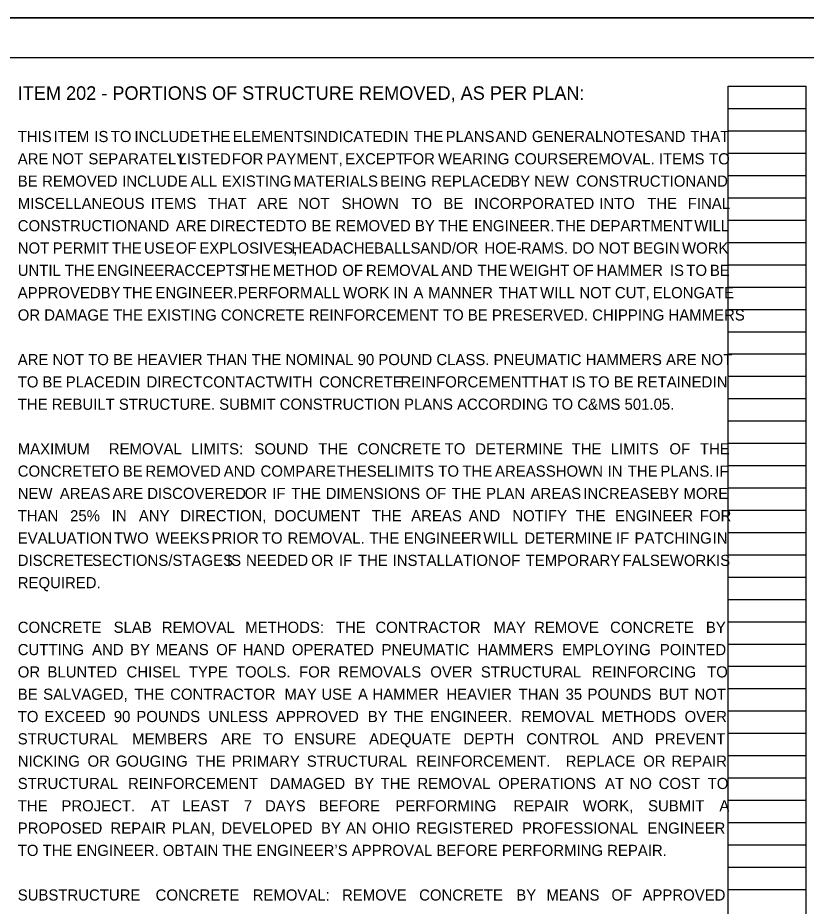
# Model space of a CAD drawing. Extents: x 0 to 64.5, y 0 to 22.
# Drawn here: x 12.29 to 22.19, y 10.85 to 22 of the extents above; entities that cross this region are included whole.
import ezdxf

# ---------------------------------------------------------------- set-up
doc = ezdxf.new("R2010")
doc.units = 0
for name, color, linetype in [('SC_Scratch1', 7, 'Continuous'), ('SH_Border', 7, 'Continuous'), ('SH_Cut_Line', 7, 'Continuous'), ('SH_Text', 7, 'Continuous')]:
    doc.layers.add(name, color=color, linetype=linetype)

msp = doc.modelspace()

# ---------------------------------------------------------------- linework, layer by layer
at = {"layer": 'SC_Scratch1'}
for p, q in [((21.207, 0.98), (21.207, 21.14)), ((21.207, 21.14), (22.187, 21.14)), ((22.187, 0.98), (22.187, 21.14)), ((21.207, 20.86), (22.187, 20.86)), ((21.207, 20.58), (22.187, 20.58)), ((21.207, 20.3), (22.187, 20.3)), ((21.207, 20.02), (22.187, 20.02)), ((21.207, 19.74), (22.187, 19.74)), ((21.207, 19.46), (22.187, 19.46)), ((21.207, 19.18), (22.187, 19.18)), ((21.207, 18.9), (22.187, 18.9)), ((21.207, 18.62), (22.187, 18.62)), ((21.207, 18.34), (22.187, 18.34)), ((21.207, 18.06), (22.187, 18.06)), ((21.207, 17.78), (22.187, 17.78)), ((21.207, 17.5), (22.187, 17.5)), ((21.207, 17.22), (22.187, 17.22)), ((21.207, 16.94), (22.187, 16.94)), ((21.207, 16.66), (22.187, 16.66)), ((21.207, 16.38), (22.187, 16.38)), ((21.207, 16.1), (22.187, 16.1)), ((21.207, 15.82), (22.187, 15.82)), ((21.207, 15.54), (22.187, 15.54)), ((21.207, 15.26), (22.187, 15.26)), ((21.207, 14.98), (22.187, 14.98)), ((21.207, 14.7), (22.187, 14.7)), ((21.207, 14.42), (22.187, 14.42)), ((21.207, 14.14), (22.187, 14.14)), ((21.207, 13.86), (22.187, 13.86)), ((21.207, 13.58), (22.187, 13.58)), ((21.207, 13.3), (22.187, 13.3)), ((21.207, 13.02), (22.187, 13.02)), ((21.207, 12.74), (22.187, 12.74)), ((21.207, 12.46), (22.187, 12.46)), ((21.207, 12.18), (22.187, 12.18)), ((21.207, 11.9), (22.187, 11.9)), ((21.207, 11.62), (22.187, 11.62)), ((21.207, 11.34), (22.187, 11.34)), ((21.207, 11.06), (22.187, 11.06))]:
    msp.add_line(p, q, dxfattribs=at)
msp.add_lwpolyline([(0, 22), (34, 22), (34, 0), (0, 0)], close=True, dxfattribs=at)
at = {"layer": 'SH_Border'}
msp.add_lwpolyline([(1.5, 21.5), (33.5, 21.5), (33.5, 0.5), (1.5, 0.5)], close=True, dxfattribs=at)
at = {"layer": 'SH_Cut_Line'}
msp.add_lwpolyline([(0, 0), (34, 0), (34, 22), (0, 22)], close=True, dxfattribs=at)

# ---------------------------------------------------------------- texts
at = {"layer": 'SH_Text'}
for s, height, p in [('ITEM 202 - PORTIONS OF STRUCTURE REMOVED, AS PER PLAN:', 0.17, (12.293, 20.97)), ('THIS ', 0.14, (12.293, 20.44)), ('ITEM ', 0.14, (12.744, 20.44)), ('IS ', 0.14, (13.254, 20.44)), ('TO ', 0.14, (13.46, 20.44)), ('INCLUDE ', 0.14, (13.757, 20.44)), ('THE ', 0.14, (14.588, 20.44)), ('ELEMENTS ', 0.14, (14.991, 20.44)), ('INDICATED ', 0.14, (15.996, 20.44)), ('IN ', 0.14, (17.011, 20.44)), ('THE ', 0.14, (17.259, 20.44)), ('PLANS ', 0.14, (17.662, 20.44)), ('AND ', 0.14, (18.289, 20.44)), ('GENERAL ', 0.14, (18.745, 20.44)), ('NOTES ', 0.14, (19.633, 20.44)), ('AND ', 0.14, (20.277, 20.44)), ('THAT ', 0.14, (20.733, 20.44)), ('ARE ', 0.14, (12.293, 20.16)), ('NOT ', 0.14, (12.719, 20.16)), ('SEPARATELY ', 0.14, (13.179, 20.16)), ('LISTED ', 0.14, (14.311, 20.16)), ('FOR ', 0.14, (14.98, 20.16)), ('PAYMENT, ', 0.14, (15.414, 20.16)), ('EXCEPT ', 0.14, (16.402, 20.16)), ('FOR ', 0.14, (17.132, 20.16)), ('WEARING ', 0.14, (17.567, 20.16)), ('COURSE ', 0.14, (18.524, 20.16)), ('REMOVAL. ', 0.14, (19.318, 20.16)), ('ITEMS ', 0.14, (20.338, 20.16)), ('TO ', 0.14, (20.968, 20.16)), ('BE ', 0.14, (12.293, 19.88)), ('REMOVED ', 0.14, (12.599, 19.88)), ('INCLUDE ', 0.14, (13.603, 19.88)), ('ALL ', 0.14, (14.462, 19.88)), ('EXISTING ', 0.14, (14.853, 19.88)), ('MATERIALS ', 0.14, (15.752, 19.88)), ('BEING ', 0.14, (16.839, 19.88)), ('REPLACED ', 0.14, (17.481, 19.88)), ('BY ', 0.14, (18.474, 19.88)), ('NEW ', 0.14, (18.774, 19.88)), ('CONSTRUCTION ', 0.14, (19.298, 19.88)), ('AND ', 0.14, (20.809, 19.88)), ('MISCELLANEOUS ', 0.14, (12.293, 19.6)), ('ITEMS ', 0.14, (13.962, 19.6)), ('THAT ', 0.14, (14.679, 19.6)), ('ARE ', 0.14, (15.298, 19.6)), ('NOT ', 0.14, (15.81, 19.6)), ('SHOWN ', 0.14, (16.356, 19.6)), ('TO ', 0.14, (17.231, 19.6)), ('BE ', 0.14, (17.634, 19.6)), ('INCORPORATED ', 0.14, (18.019, 19.6)), ('INTO ', 0.14, (19.589, 19.6)), ('THE ', 0.14, (20.191, 19.6)), ('FINAL ', 0.14, (20.7, 19.6)), ('CONSTRUCTION ', 0.14, (12.293, 19.32)), ('AND ', 0.14, (13.799, 19.32)), ('ARE ', 0.14, (14.277, 19.32)), ('DIRECTED ', 0.14, (14.704, 19.32)), ('TO ', 0.14, (15.659, 19.32)), ('BE ', 0.14, (15.978, 19.32)), ('REMOVED ', 0.14, (16.278, 19.32)), ('BY ', 0.14, (17.277, 19.32)), ('THE ', 0.14, (17.571, 19.32)), ('ENGINEER. ', 0.14, (17.996, 19.32)), ('THE ', 0.14, (19.046, 19.32)), ('DEPARTMENT ', 0.14, (19.471, 19.32)), ('WILL ', 0.14, (20.783, 19.32)), ('NOT ', 0.14, (12.293, 19.04)), ('PERMIT ', 0.14, (12.732, 19.04)), ('THE ', 0.14, (13.475, 19.04)), ('USE ', 0.14, (13.877, 19.04)), ('OF ', 0.14, (14.276, 19.04)), ('EXPLOSIVES, ', 0.14, (14.572, 19.04)), ('HEADACHE ', 0.14, (15.728, 19.04)), ('BALLS ', 0.14, (16.764, 19.04)), ('AND/OR ', 0.14, (17.344, 19.04)), ('HOE-', 0.14, (18.149, 19.04)), ('RAMS. ', 0.14, (18.606, 19.04)), ('DO ', 0.14, (19.248, 19.04)), ('NOT ', 0.14, (19.578, 19.04)), ('BEGIN ', 0.14, (20.016, 19.04)), ('WORK ', 0.14, (20.628, 19.04)), ('UNTIL ', 0.14, (12.293, 18.76)), ('THE ', 0.14, (12.883, 18.76)), ('ENGINEER ', 0.14, (13.287, 18.76)), ('ACCEPTS ', 0.14, (14.259, 18.76)), ('THE ', 0.14, (15.091, 18.76)), ('METHOD ', 0.14, (15.494, 18.76)), ('OF ', 0.14, (16.366, 18.76)), ('REMOVAL ', 0.14, (16.662, 18.76)), ('AND ', 0.14, (17.606, 18.76)), ('THE ', 0.14, (18.062, 18.76)), ('WEIGHT ', 0.14, (18.465, 18.76)), ('OF ', 0.14, (19.259, 18.76)), ('HAMMER ', 0.14, (19.556, 18.76)), ('IS ', 0.14, (20.476, 18.76)), ('TO ', 0.14, (20.682, 18.76)), ('BE ', 0.14, (20.978, 18.76)), ('APPROVED ', 0.14, (12.293, 18.48)), ('BY ', 0.14, (13.333, 18.48)), ('THE ', 0.14, (13.611, 18.48)), ('ENGINEER. ', 0.14, (14.021, 18.48)), ('PERFORM ', 0.14, (15.055, 18.48)), ('ALL ', 0.14, (16.005, 18.48)), ('WORK ', 0.14, (16.375, 18.48)), ('IN ', 0.14, (17.005, 18.48)), ('A ', 0.14, (17.259, 18.48)), ('MANNER ', 0.14, (17.444, 18.48)), ('THAT ', 0.14, (18.328, 18.48)), ('WILL ', 0.14, (18.847, 18.48)), ('NOT ', 0.14, (19.341, 18.48)), ('CUT, ', 0.14, (19.786, 18.48)), ('ELONGATE ', 0.14, (20.262, 18.48)), ('OR DAMAGE THE EXISTING CONCRETE REINFORCEMENT TO BE PRESERVED. CHIPPING HAMMERS ', 0.14, (12.293, 18.2)), ('ARE NOT TO BE HEAVIER THAN THE NOMINAL 90 POUND CLASS. PNEUMATIC HAMMERS ARE NOT ', 0.14, (12.293, 17.64)), ('TO ', 0.14, (12.293, 17.36)), ('BE ', 0.14, (12.603, 17.36)), ('PLACED ', 0.14, (12.895, 17.36)), ('IN ', 0.14, (13.647, 17.36)), ('DIRECT ', 0.14, (13.909, 17.36)), ('CONTACT ', 0.14, (14.612, 17.36)), ('WITH ', 0.14, (15.513, 17.36)), ('CONCRETE ', 0.14, (16.074, 17.36)), ('REINFORCEMENT ', 0.14, (17.095, 17.36)), ('THAT ', 0.14, (18.715, 17.36)), ('IS ', 0.14, (19.241, 17.36)), ('TO ', 0.14, (19.46, 17.36)), ('BE ', 0.14, (19.77, 17.36)), ('RETAINED ', 0.14, (20.062, 17.36)), ('IN ', 0.14, (21.013, 17.36)), ('THE REBUILT STRUCTURE. SUBMIT CONSTRUCTION PLANS ACCORDING TO C&MS 501.05. ', 0.14, (12.293, 17.08)), ('MAXIMUM ', 0.14, (12.293, 16.52)), ('REMOVAL ', 0.14, (13.436, 16.52)), ('LIMITS: ', 0.14, (14.467, 16.52)), ('SOUND ', 0.14, (15.263, 16.52)), ('THE ', 0.14, (16.064, 16.52)), ('CONCRETE ', 0.14, (16.554, 16.52)), ('TO ', 0.14, (17.65, 16.52)), ('DETERMINE ', 0.14, (18.033, 16.52)), ('THE ', 0.14, (19.243, 16.52)), ('LIMITS ', 0.14, (19.733, 16.52)), ('OF ', 0.14, (20.47, 16.52)), ('THE ', 0.14, (20.853, 16.52)), ('CONCRETE ', 0.14, (12.293, 16.24)), ('TO ', 0.14, (13.308, 16.24)), ('BE ', 0.14, (13.611, 16.24)), ('REMOVED ', 0.14, (13.895, 16.24)), ('AND ', 0.14, (14.878, 16.24)), ('COMPARE ', 0.14, (15.34, 16.24)), ('THESE ', 0.14, (16.298, 16.24)), ('LIMITS ', 0.14, (16.913, 16.24)), ('TO ', 0.14, (17.57, 16.24)), ('THE ', 0.14, (17.873, 16.24)), ('AREAS ', 0.14, (18.282, 16.24)), ('SHOWN ', 0.14, (18.919, 16.24)), ('IN ', 0.14, (19.693, 16.24)), ('THE ', 0.14, (19.948, 16.24)), ('PLANS. ', 0.14, (20.357, 16.24)), ('IF ', 0.14, (21.046, 16.24)), ('NEW ', 0.14, (12.293, 15.96)), ('AREAS ', 0.14, (12.821, 15.96)), ('ARE ', 0.14, (13.482, 15.96)), ('DISCOVERED ', 0.14, (13.918, 15.96)), ('OR ', 0.14, (15.141, 15.96)), ('IF ', 0.14, (15.486, 15.96)), ('THE ', 0.14, (15.724, 15.96)), ('DIMENSIONS ', 0.14, (16.157, 15.96)), ('OF ', 0.14, (17.41, 15.96)), ('THE ', 0.14, (17.737, 15.96)), ('PLAN ', 0.14, (18.17, 15.96)), ('AREAS ', 0.14, (18.728, 15.96)), ('INCREASE ', 0.14, (19.389, 15.96)), ('BY ', 0.14, (20.343, 15.96)), ('MORE ', 0.14, (20.646, 15.96)), ('THAN ', 0.14, (12.293, 15.68)), ('25% ', 0.14, (12.95, 15.68)), ('IN ', 0.14, (13.473, 15.68)), ('ANY ', 0.14, (13.813, 15.68)), ('DIRECTION, ', 0.14, (14.332, 15.68)), ('DOCUMENT ', 0.14, (15.51, 15.68)), ('THE ', 0.14, (16.735, 15.68)), ('AREAS ', 0.14, (17.23, 15.68)), ('AND ', 0.14, (17.952, 15.68)), ('NOTIFY ', 0.14, (18.499, 15.68)), ('THE ', 0.14, (19.294, 15.68)), ('ENGINEER ', 0.14, (19.788, 15.68)), ('FOR ', 0.14, (20.852, 15.68)), ('EVALUATION ', 0.14, (12.293, 15.4)), ('TWO ', 0.14, (13.5, 15.4)), ('WEEKS ', 0.14, (14.024, 15.4)), ('PRIOR ', 0.14, (14.725, 15.4)), ('TO ', 0.14, (15.356, 15.4)), ('REMOVAL. ', 0.14, (15.679, 15.4)), ('THE ', 0.14, (16.706, 15.4)), ('ENGINEER ', 0.14, (17.136, 15.4)), ('WILL ', 0.14, (18.135, 15.4)), ('DETERMINE ', 0.14, (18.65, 15.4)), ('IF ', 0.14, (19.799, 15.4)), ('PATCHING ', 0.14, (20.033, 15.4)), ('IN ', 0.14, (21.013, 15.4)), ('DISCRETE ', 0.14, (12.293, 15.12)), ('SECTIONS/STAGES ', 0.14, (13.225, 15.12)), ('IS ', 0.14, (14.919, 15.12)), ('NEEDED ', 0.14, (15.157, 15.12)), ('OR ', 0.14, (15.976, 15.12)), ('IF ', 0.14, (16.323, 15.12)), ('THE ', 0.14, (16.562, 15.12)), ('INSTALLATION ', 0.14, (16.997, 15.12)), ('OF ', 0.14, (18.339, 15.12)), ('TEMPORARY ', 0.14, (18.667, 15.12)), ('FALSEWORK ', 0.14, (19.882, 15.12)), ('IS ', 0.14, (21.055, 15.12)), ('REQUIRED.', 0.14, (12.293, 14.84)), ('CONCRETE ', 0.14, (12.293, 14.28)), ('SLAB ', 0.14, (13.496, 14.28)), ('REMOVAL ', 0.14, (14.101, 14.28)), ('METHODS: ', 0.14, (15.148, 14.28)), ('THE ', 0.14, (16.285, 14.28)), ('CONTRACTOR ', 0.14, (16.781, 14.28)), ('MAY ', 0.14, (18.263, 14.28)), ('REMOVE ', 0.14, (18.773, 14.28)), ('CONCRETE ', 0.14, (19.726, 14.28)), ('BY ', 0.14, (20.928, 14.28)), ('CUTTING ', 0.14, (12.293, 14)), ('AND ', 0.14, (13.226, 14)), ('BY ', 0.14, (13.703, 14)), ('MEANS ', 0.14, (14.024, 14)), ('OF ', 0.14, (14.783, 14)), ('HAND ', 0.14, (15.115, 14)), ('OPERATED ', 0.14, (15.733, 14)), ('PNEUMATIC ', 0.14, (16.858, 14)), ('HAMMERS ', 0.14, (18.06, 14)), ('EMPLOYING ', 0.14, (19.123, 14)), ('POINTED ', 0.14, (20.35, 14)), ('OR ', 0.14, (12.293, 13.72)), ('BLUNTED ', 0.14, (12.666, 13.72)), ('CHISEL ', 0.14, (13.658, 13.72)), ('TYPE ', 0.14, (14.44, 13.72)), ('TOOLS. ', 0.14, (15.03, 13.72)), ('FOR ', 0.14, (15.823, 13.72)), ('REMOVALS ', 0.14, (16.315, 13.72)), ('OVER ', 0.14, (17.47, 13.72)), ('STRUCTURAL ', 0.14, (18.104, 13.72)), ('REINFORCING ', 0.14, (19.495, 13.72)), ('TO ', 0.14, (20.943, 13.72)), ('BE ', 0.14, (12.293, 13.44)), ('SALVAGED, ', 0.14, (12.612, 13.44)), ('THE ', 0.14, (13.757, 13.44)), ('CONTRACTOR ', 0.14, (14.206, 13.44)), ('MAY ', 0.14, (15.64, 13.44)), ('USE ', 0.14, (16.103, 13.44)), ('A ', 0.14, (16.563, 13.44)), ('HAMMER ', 0.14, (16.744, 13.44)), ('HEAVIER ', 0.14, (17.671, 13.44)), ('THAN ', 0.14, (18.577, 13.44)), ('35 ', 0.14, (19.167, 13.44)), ('POUNDS ', 0.14, (19.442, 13.44)), ('BUT ', 0.14, (20.336, 13.44)), ('NOT ', 0.14, (20.785, 13.44)), ('TO ', 0.14, (12.293, 13.16)), ('EXCEED ', 0.14, (12.627, 13.16)), ('90 ', 0.14, (13.498, 13.16)), ('POUNDS ', 0.14, (13.781, 13.16)), ('UNLESS ', 0.14, (14.684, 13.16)), ('APPROVED ', 0.14, (15.533, 13.16)), ('BY ', 0.14, (16.686, 13.16)), ('THE ', 0.14, (17.01, 13.16)), ('ENGINEER. ', 0.14, (17.467, 13.16)), ('REMOVAL ', 0.14, (18.609, 13.16)), ('METHODS ', 0.14, (19.617, 13.16)), ('OVER ', 0.14, (20.661, 13.16)), ('STRUCTURAL ', 0.14, (12.293, 12.88)), ('MEMBERS ', 0.14, (13.729, 12.88)), ('ARE ', 0.14, (14.843, 12.88)), ('TO ', 0.14, (15.369, 12.88)), ('ENSURE ', 0.14, (15.761, 12.88)), ('ADEQUATE ', 0.14, (16.701, 12.88)), ('DEPTH ', 0.14, (17.887, 12.88)), ('CONTROL ', 0.14, (18.674, 12.88)), ('AND ', 0.14, (19.751, 12.88)), ('PREVENT ', 0.14, (20.288, 12.88)), ('NICKING ', 0.14, (12.293, 12.6)), ('OR ', 0.14, (13.169, 12.6)), ('GOUGING ', 0.14, (13.522, 12.6)), ('THE ', 0.14, (14.528, 12.6)), ('PRIMARY ', 0.14, (14.98, 12.6)), ('STRUCTURAL ', 0.14, (15.92, 12.6)), ('REINFORCEMENT.  ', 0.14, (17.292, 12.6)), ('REPLACE ', 0.14, (19.168, 12.6)), ('OR ', 0.14, (20.141, 12.6)), ('REPAIR ', 0.14, (20.495, 12.6)), ('STRUCTURAL ', 0.14, (12.293, 12.32)), ('REINFORCEMENT ', 0.14, (13.677, 12.32)), ('DAMAGED ', 0.14, (15.455, 12.32)), ('BY ', 0.14, (16.516, 12.32)), ('THE ', 0.14, (16.845, 12.32)), ('REMOVAL ', 0.14, (17.308, 12.32)), ('OPERATIONS ', 0.14, (18.322, 12.32)), ('AT ', 0.14, (19.662, 12.32)), ('NO ', 0.14, (19.97, 12.32)), ('COST ', 0.14, (20.335, 12.32)), ('TO ', 0.14, (20.95, 12.32)), ('THE ', 0.14, (12.293, 12.04)), ('PROJECT. ', 0.14, (12.841, 12.04)), ('AT ', 0.14, (13.964, 12.04)), ('LEAST ', 0.14, (14.356, 12.04)), ('7 ', 0.14, (15.131, 12.04)), ('DAYS ', 0.14, (15.396, 12.04)), ('BEFORE ', 0.14, (16.07, 12.04)), ('PERFORMING ', 0.14, (17.031, 12.04)), ('REPAIR ', 0.14, (18.513, 12.04)), ('WORK, ', 0.14, (19.383, 12.04)), ('SUBMIT ', 0.14, (20.202, 12.04)), ('A ', 0.14, (21.097, 12.04)), ('PROPOSED ', 0.14, (12.293, 11.76)), ('REPAIR ', 0.14, (13.457, 11.76)), ('PLAN, ', 0.14, (14.227, 11.76)), ('DEVELOPED ', 0.14, (14.847, 11.76)), ('BY ', 0.14, (16.098, 11.76)), ('AN ', 0.14, (16.411, 11.76)), ('OHIO ', 0.14, (16.738, 11.76)), ('REGISTERED ', 0.14, (17.293, 11.76)), ('PROFESSIONAL ', 0.14, (18.62, 11.76)), ('ENGINEER ', 0.14, (20.194, 11.76)), ('TO THE ENGINEER. OBTAIN THE ENGINEER’S APPROVAL BEFORE PERFORMING REPAIR.', 0.14, (12.293, 11.48)), ('SUBSTRUCTURE ', 0.14, (12.293, 10.92)), ('CONCRETE ', 0.14, (14.023, 10.92)), ('REMOVAL: ', 0.14, (15.241, 10.92)), ('REMOVE ', 0.14, (16.362, 10.92)), ('CONCRETE ', 0.14, (17.33, 10.92)), ('BY ', 0.14, (18.549, 10.92)), ('MEANS ', 0.14, (18.927, 10.92)), ('OF ', 0.14, (19.743, 10.92)), ('APPROVED ', 0.14, (20.132, 10.92))]:
    msp.add_text(s, height=height, dxfattribs=at).set_placement(p)

doc.saveas('drawing.dxf')
